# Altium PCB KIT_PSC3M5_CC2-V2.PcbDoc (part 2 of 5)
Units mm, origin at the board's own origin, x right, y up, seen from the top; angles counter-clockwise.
Board outline 131.5 x 87 mm, 6 copper layers (Top Layer, Int1 (GND), Int2 (Sign), Int3 (Sign), Int4 (PWR), Bottom Layer), stack 1.551 mm thick; 371 components, 253 nets, 1359 pads, 837 vias.
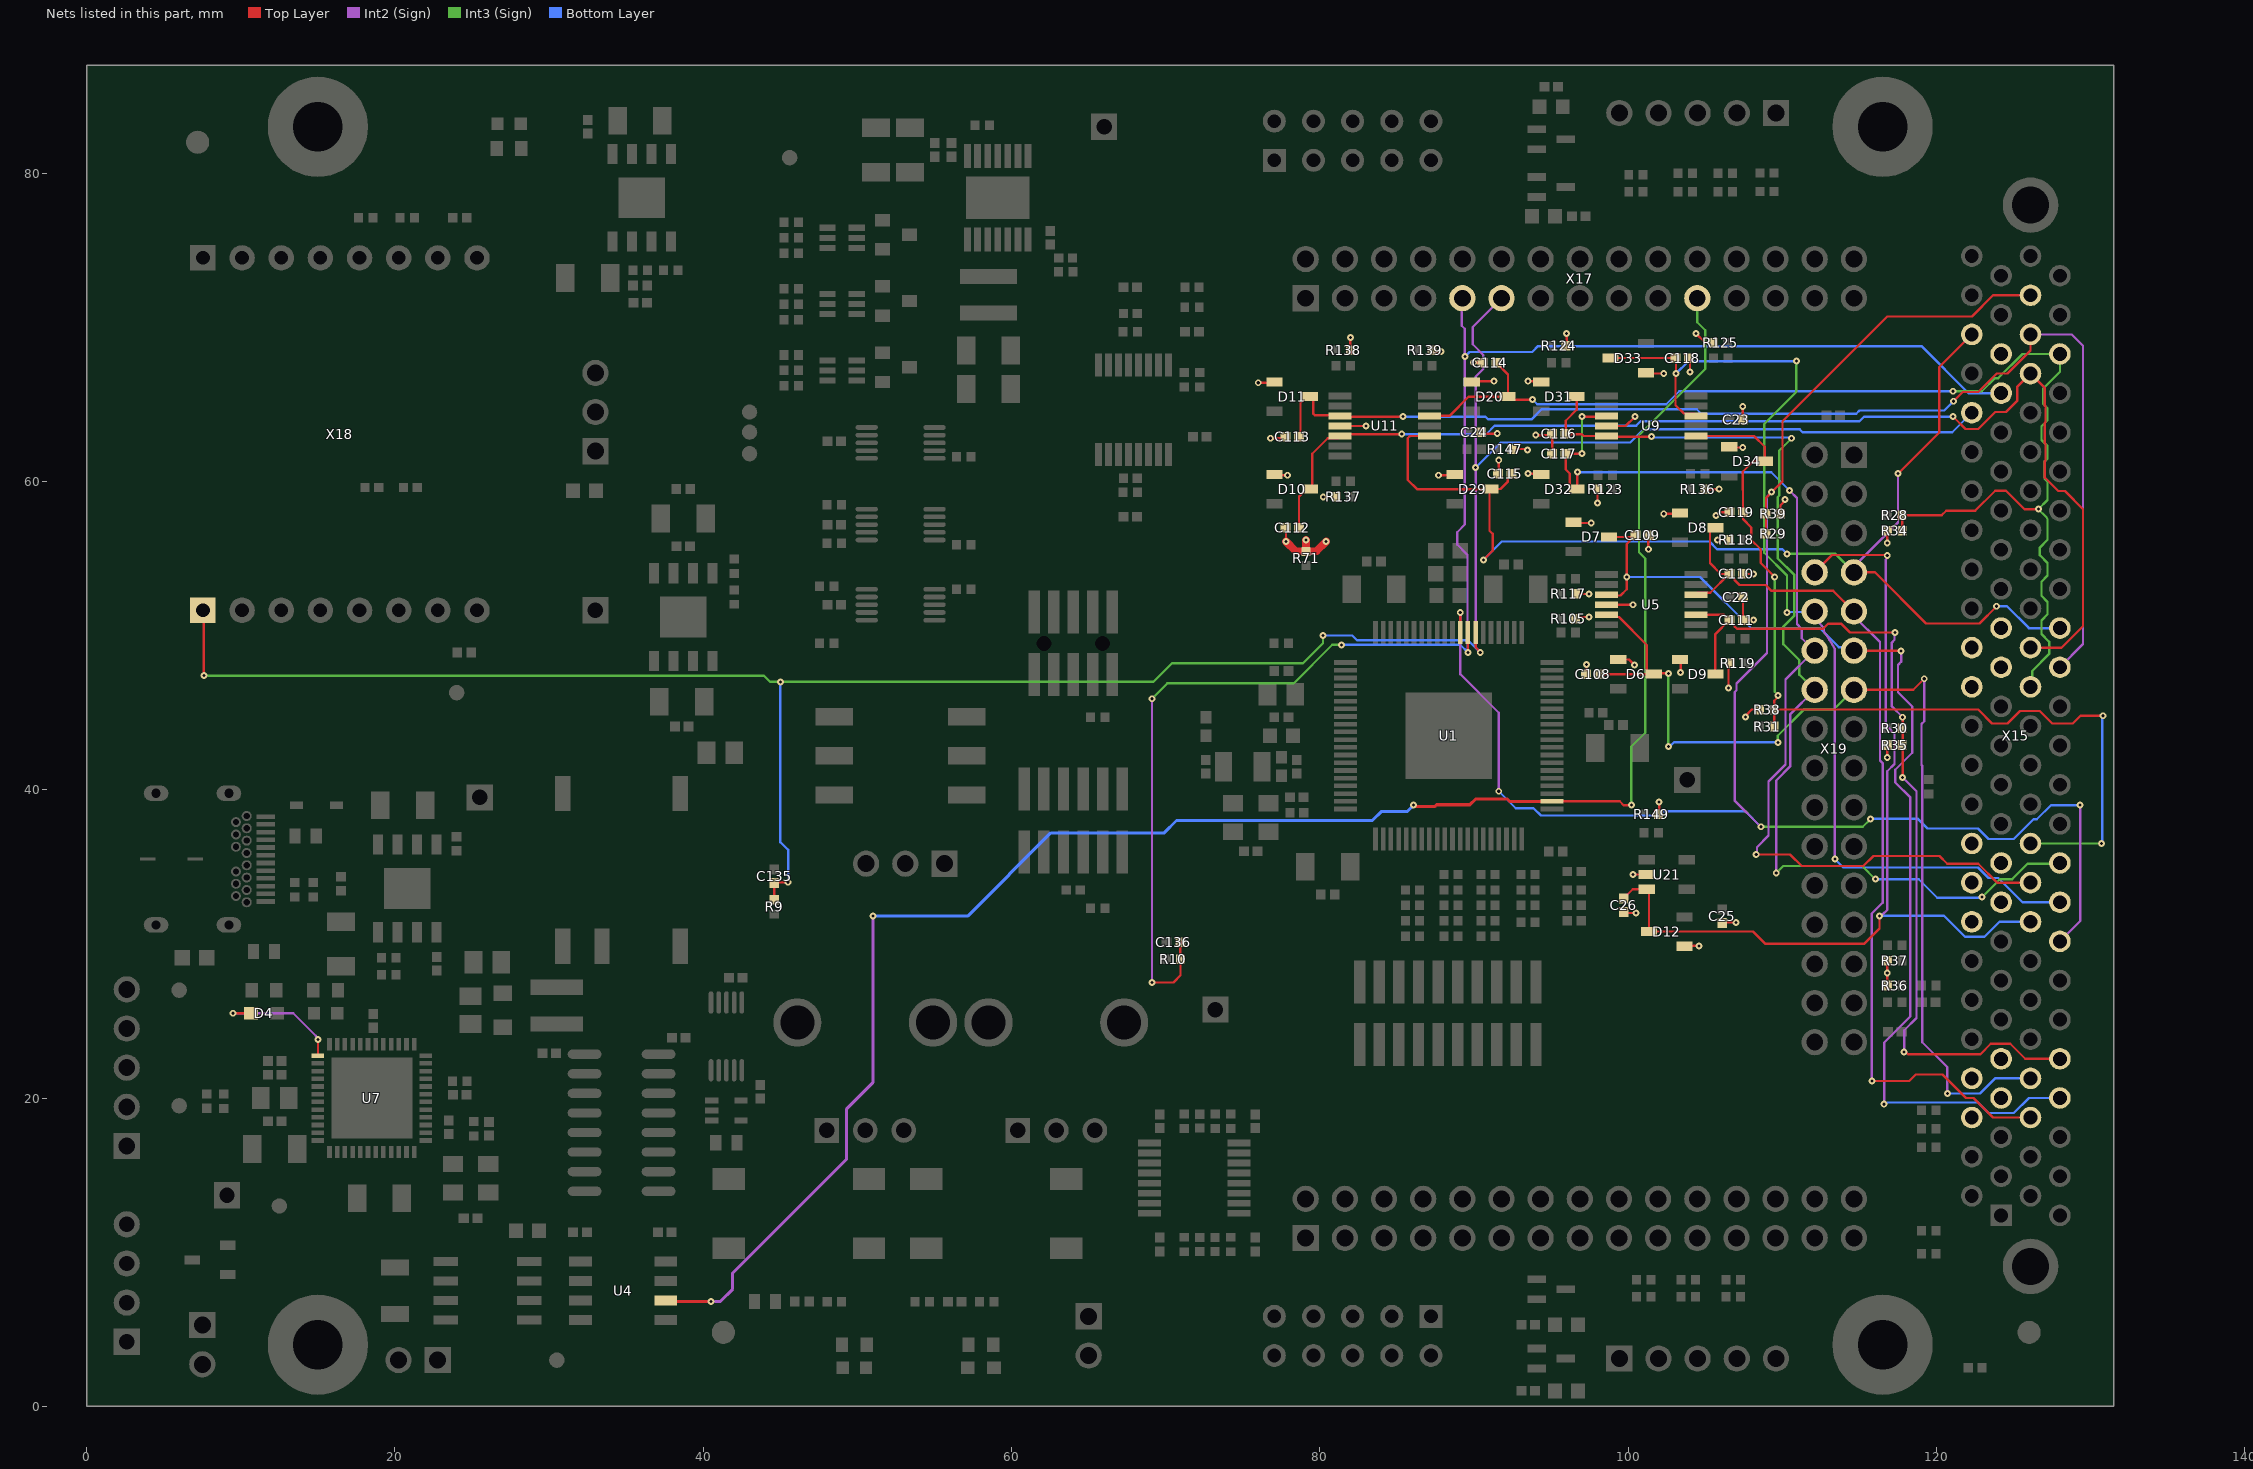
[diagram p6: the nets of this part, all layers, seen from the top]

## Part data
ADJ_1 ADJ_2 ADJ_3: library part Fiducial_Round_1.5mm, "Fiducial Round 1.5mm Copper, 3mm Soldermask", PartNumber=-NoPartNumber-
C1 C6 C7 C8 C9 C10 C14 C16 C28 C43 C75 C76 C127 C132: library part 507459, "CAP / CERA / 100nF / 50V / 10% / X7R (EIA) / -55°C to 125°C / 0402(1005) / SMD / -", Manufacturer="TDK Corporation", Package Description="Capacitor,non-polarized,Chip;1.00mm L X 0.50mm W X 0.60mm H", Package Imperial=0402, Package Metric=1005, Temperature max=125, Temperature min=-55, Temperature Range=Military, Tolerance Neg=10%, Voltage DC (max)=50V
C2 C17 C21 C107: library part 668123, "CAP / CERA / 1uF / 25V / 10% / X7R (EIA) / -55°C to 125°C / 0603(1608) / SMD / -", Manufacturer=Samsung, Package Description="Capacitor,non-polarized,Chip;1.60mm L X 0.80mm W X 0.90mm H", Package Imperial=0603, Package Metric=1608, Supplier Part Number 1=3013415, Temperature max=125, Temperature min=-55, Temperature Range=Military, Tolerance Neg=10%, Voltage DC (max)=25V
C3 C4 C5 C11 C13 C15 C42 C44 C45 C47 C100 C101 C105 C106 C128 C130: library part 282249, "CAP / CERA / 10uF / 50V / 20% / X5R (EIA) / -55°C to 85°C / 1206(3216) / SMD / -", Manufacturer=MuRata, Package Description="Capacitor,non-polarized,Chip;3.20mm L X 1.60mm W X 1.80mm H", Package Imperial=1206, Package Metric=3216, Supplier Part Number 1=2611954, Temperature max=85, Temperature min=-55, Temperature Range=Military, Tolerance Neg=20%, Voltage DC (max)=50V
C12 C41 C126: library part 264563, "CAP / CERA / 10nF / 16V / 5% / X7R (EIA) / -55°C to 125°C / 0402(1005) / SMD / -", Legacy PartNumber=CAP01001706, Manufacturer=MuRata, Package Description="Capacitor,non-polarized,Chip;1.00mm L X 0.50mm W X 0.55mm H", Package Imperial=0402, Package Metric=1005, Temperature max=125, Temperature min=-55, Temperature Range=Military, Tolerance Neg=5%, Voltage DC (max)=16V
C18 C51 C62 C64 C80: library part 673682, "CAP / CERA / 4.7uF / 25V / 20% / X7R (EIA) / -55°C to 125°C / 0805 / SMD / -", Manufacturer=Yageo, Package Description="Capacitor,non-polarized,Chip;2.00mm L X 1.25mm W X 1.45mm H", Supplier Part Number 1=3760019, Temperature max=125, Temperature min=-55, Temperature Range=Military, Tolerance Neg=20%, Voltage DC (max)=25V
C19 C20 C22 C23 C24 C25 C29 C32 C34 C36 C38 C40 C46 C48 C49 C50 C52 C53 C63 C65 C77 C78 C81 C82 C102 C104 C124 C125 C129 C131: library part 310625, "CAP / CERA / 100nF / 50V / 10% / X7R (EIA) / -55°C to 125°C / 0402(1005) / SMD / -", Legacy PartNumber=CAP01010920, Manufacturer=MuRata, Package Description="Capacitor,non-polarized,Chip;1.00mm L X 0.50mm W X 0.55mm H", Package Imperial=0402, Package Metric=1005, Supplier Part Number 1=2611912, Temperature max=125, Temperature min=-55, Temperature Range=Military, Tolerance Neg=10%, Voltage DC (max)=50V
C26 C108 C109 C110 C112 C113 C114 C116 C117 C118: library part 287086, "CAP / CERA / 1nF / 50V / 10% / X7R (EIA) / -55°C to 125°C / 0402(1005) / SMD / -", Legacy PartNumber=CAP01006490, Manufacturer=MuRata, Package Description="Capacitor,non-polarized,Chip;1.00mm L X 0.50mm W X 0.55mm H", Package Imperial=0402, Package Metric=1005, Temperature max=125, Temperature min=-55, Temperature Range=Military, Tolerance Neg=10%, Voltage DC (max)=50V
C33 C35 C37 C39: library part 668123, "CAP / CERA / 1uF / 25V / 10% / X7R (EIA) / -55°C to 125°C / 0603 / SMD / -", Manufacturer=Samsung, Package Description="Capacitor,non-polarized,Chip;1.60mm L X 0.80mm W X 0.90mm H", Supplier Part Number 1=3013415, Temperature max=125, Temperature min=-55, Temperature Range=Military, Tolerance Neg=10%, Voltage DC (max)=25V
C70 C73 C87 C88: library part 287311, "CAP / CERA / 15pF / 50V / 2% / C0G (EIA) / NP0 / -55°C to 125°C / 0402(1005) / SMD / -", Legacy PartNumber=CAP01006535, Manufacturer=MuRata, Package Description="Capacitor,non-polarized,Chip;1.00mm L X 0.50mm W X 0.55mm H", Package Imperial=0402, Package Metric=1005, Temperature max=125, Temperature min=-55, Temperature Range=Military, Tolerance Neg=2%, Voltage DC (max)=50V
C74 C89 C90 C94 C95 C96 C135 C136 C137 C138 C139: library part 289336, "CAP / CERA / 15nF / 50V / 20% / X7R (EIA) / -55°C to 125°C / 0402(1005) / SMD / -", Legacy PartNumber=CAP01006940, Manufacturer=MuRata, Package Description="Capacitor,non-polarized,Chip;1.00mm L X 0.50mm W X 0.55mm H", Package Imperial=0402, Package Metric=1005, Temperature max=125, Temperature min=-55, Temperature Range=Military, Tolerance Neg=20%, Voltage DC (max)=50V
C85 C86: library part 287356, "CAP / CERA / 18pF / 50V / 1% / C0G (EIA) / NP0 / -55°C to 125°C / 0402(1005) / SMD / -", Legacy PartNumber=CAP01006544, Manufacturer=MuRata, Package Description="Capacitor,non-polarized,Chip;1.00mm L X 0.50mm W X 0.55mm H", Package Imperial=0402, Package Metric=1005, Temperature max=125, Temperature min=-55, Temperature Range=Military, Tolerance Neg=1%, Voltage DC (max)=50V
C103: library part 289386, "CAP / CERA / 2.2nF / 50V / 20% / X7R (EIA) / -55°C to 125°C / 0402(1005) / SMD / -", Legacy PartNumber=CAP01006950, Manufacturer=MuRata, Package Description="Capacitor,non-polarized,Chip;1.00mm L X 0.50mm W X 0.55mm H", Package Imperial=0402, Package Metric=1005, Temperature max=125, Temperature min=-55, Temperature Range=Military, Tolerance Neg=20%, Voltage DC (max)=50V
C111 C115 C119: library part 286936, "CAP / CERA / 22pF / 50V / 5% / C0G (EIA) / NP0 / -55°C to 125°C / 0402(1005) / SMD / -", Legacy PartNumber=CAP01006460, Manufacturer=MuRata, Package Description="Capacitor,non-polarized,Chip;1.00mm L X 0.50mm W X 0.55mm H", Package Imperial=0402, Package Metric=1005, Temperature max=125, Temperature min=-55, Temperature Range=Military, Tolerance Neg=5%, Voltage DC (max)=50V
D1: library part 678278, "Chip LED, 589nm, Yellow, Electronic Equipment Applications", Manufacturer="OSRAM Opto Semiconductors", Package Description="LED,Side Concave;2 pin,1.60mm W X 0.80mm L X 0.40mm H", Temperature max=85, Temperature min=-30, Temperature Range=Military, Voltage DC (max)=na
D2 D4: library part 494911, "ChipLED 0603, Red, 633nm, Temp Raneg(-30 to 85°C)", Manufacturer="OSRAM Opto Semiconductors", Package Description="LED,Side Concave;2 pin,1.60mm W X 0.80mm L X 0.80mm H", Temperature max=85, Temperature min=-30, Temperature Range=Military, Voltage DC (max)=na
D3 D5: library part 678273, "Chip LED, 573nm, Green, Electronic Equipment Applications", Manufacturer="OSRAM Opto Semiconductors", Package Description="LED,Side Concave;2 pin,1.60mm W X 0.80mm L X 0.40mm H", Supplier Part Number 1=2575345, Temperature max=85, Temperature min=-30, Temperature Range=Military, Voltage DC (max)=na
D6 D7 D8 D9 D10 D11 D12 D20 D29 D31 D32 D33 D34: library part 394146, "Dual Series Small Signal Schottky Diodes", Legacy PartNumber=DIO01300188, Manufacturer=Vishay, Package Description="SOT,0.95mm pitch;3 pin,1.315mm W X 2.95mm L X 1.15mm H body", Supplier Part Number 1=1612328, Temperature max=125, Temperature min=-55, Temperature Range=Military, Voltage DC (max)=na
D21: library part 420617, "Medium Power AF Schottky Diode", Legacy PartNumber=IFX01400145, Manufacturer="Infineon Technologies", Package Description=SOD323, Temperature max=125, Temperature min=-65, Temperature Range=Military, Voltage DC (max)=na
D30: library part 527432, "CAN bus ESD protection diode", Manufacturer=Nexperia, Package Description="SOT,0.95mm pitch;3 pin,1.30mm W X 2.90mm L X 1.10mm H body", Supplier Part Number 1=1510712, Temperature max=150, Temperature min=-55, Temperature Range=Military, Voltage DC (max)=na
JP1 X28 X30: library part 382904, "Through hole .025 SQ Post Header, 2.54mm pitch, 2 pin, vertical, single row", Legacy PartNumber=CON01500574, Manufacturer=Samtec, Package Description="Header,vertical,2.54mm pitch;0.64mm lead width,2 pins,1 row,2 pins per row,5.08mm L X 2.54mm W X 8.636mm H body", Supplier Part Number 1=2667448, Temperature max=125, Temperature min=-55, Temperature Range=Military, Voltage DC (max)=na
L1: library part BLM18PG600SN1D, "FERRITE, SMD, 60 OHM, 0603", Manufacturer=Murata, PartNumber=01.30.0224.0, Supplier Part Number 1=490-1036-2-ND
L2 L4: library part BLM18KG102SN1D, "FERRITE, SMD, 1000 OHM, 0.8A, 0603", Manufacturer=Murata, PartNumber=01.30.0521.0
L3: library part 325876, "IND / STD / 4.7uH / 5.1A / 20% / -40°C to 125°C / 44.1R / SMD Type / Inductor,Chip;4.00mm L X 4.00mm W X 3.10mm H / SMD / -", Legacy PartNumber=IND00702665, Manufacturer=Coilcraft, Package Description="Inductor,Chip;4.00mm L X 4.00mm W X 3.10mm H", Supplier Part Number 1=2289056, Temperature max=125, Temperature min=-40, Temperature Range=Automotive, Tolerance Neg=20%, Voltage DC (max)=na
L5: "FERRITE, SMD, 30 OHM, 4000mA, 0805", Manufacturer=Murata, PartNumber=01.30.0266.0, Supplier Part Number 1=490-1052-1-ND
L6: "2.2uH - Isat 5.6A", Manufacturer=Coilcraft, PartNumber=01.30.0326.0
MH1 MH2 MH3 MH4: library part Mounting_Hole_M3, PartNumber=-NoPartNumber-
Q1 Q8 Q9 Q10: "PNP-Digital Transistor  50V, 100mA, R1=R2=47k, SOT-323", Manufacturer="Infineon Technologies AG", Manufacturer (2nd Source)=Nexperia, ManufacturerPartNo (2nd Source)=PDTA144EU,115, PartNumber=00.94.0133.0, Supplier Part Number 1=2156-PDTA144EU,115-ND
Q2 Q5 Q7: library part BCM8575BS,115, "Dual PNP/PNP, Vceo -45V, Ic -100mA, hFE 290, AEC-Q", Manufacturer=Nexperia, ManufacturerPartNo=BCM857BS,115, PartNumber=00.94.0374.0, Supplier Part Number 1=1727-4883-2-ND
Q3 Q4 Q6: library part 400833, "HEXFET P-Channel Power MOSFET, 20V, 3.7A", Manufacturer="Infineon Technologies", Package Description="SOT,0.95mm pitch;3 pin,1.30mm W X 2.92mm L X 1.12mm H body", Supplier Part Number 1=2363354, Temperature max=150, Temperature min=-55, Temperature Range=Military, Voltage DC (max)=na
R1 R2: library part Solderbridge_2Pad_0R_0402, "SMD solderbridge, 2 Pads, 0R resistor populated, 0402 size", PartNumber=01.02.0902.0
R3 R4 R8 R11 R12 R13 R15 R17 R25 R26 R47 R56 R58 R60 R62 R71 R72 R74 R76 R78 R79 R80 R81 R82 R83 R87 R88 R89 R90 R92 R94 R95 R96 R97 R98 R103 R104 R108: library part 327372, "RES / STD / 0R / 63mW / 0R / 0ppm/K / -55°C to 155°C / 0402(1005) / SMD / -", Legacy PartNumber=RES00000001, Manufacturer=Yageo, Package Imperial=0402, Package Metric=1005, Temperature max=155, Temperature min=-55, Temperature Range=Military, Voltage DC (max)=50V
R5 R53: library part 345982, "RES / STD / 4.7k / 100mW / 1% / 100ppm/K / -55°C to 155°C / 0603(1608) / SMD / -", Legacy PartNumber=RES01801219, Manufacturer=Vishay, Package Imperial=0603, Package Metric=1608, Temperature max=155, Temperature min=-55, Temperature Range=Military, Tolerance Neg=1%, Voltage DC (max)=75V
R6 R7: library part 675198, "RES / VAR / 10k / 50mW / 20% / - / -10°C to 50°C /  THT, 2.5 mm pitch, 11.80 mm L X 10 mm W X 20.5 mm H body / - / -", Manufacturer=Bourns, Package Description="Potentiometer; THT, 2.5 mm pitch, 11.80 mm L X 10 mm W X 20.5 mm H body", Supplier Part Number 1=2519610, Temperature max=50, Temperature min=-10, Temperature Range=Military, Tolerance Neg=20%, Voltage DC (max)=20V
R9 R10 R126: library part 327441, "RES / STD / 100R / 63mW / 1% / 100ppm/K / -55°C to 155°C / 0402(1005) / SMD / -", Manufacturer=Yageo, Package Description="Resistor,Chip;1.00mm L X 0.50mm W X 0.40mm H", Package Imperial=0402, Package Metric=1005, Supplier Part Number 1=9239111, Temperature max=155, Temperature min=-55, Temperature Range=Military, Tolerance Neg=1%
R14 R24 R70 R75 R91 R99 R114 R115 R116 R120 R121 R122 R127 R128 R129 R130 R140 R143 R144 R145: library part 342167, "RES / STD / 10k / 63mW / 1% / 100ppm/K / -55°C to 155°C / 0402(1005) / SMD / -", Legacy PartNumber=RES01800457, Manufacturer=Vishay, Package Imperial=0402, Package Metric=1005, Temperature max=155, Temperature min=-55, Temperature Range=Military, Tolerance Neg=1%, Voltage DC (max)=50V
R16 R28 R29 R30 R31 R40 R41 R42 R43 R44 R45 R46 R51 R55 R57 R59 R61 R148 R150 R152: library part 341597, "RES / STD / 1k / 63mW / 1% / 100ppm/K / -55°C to 155°C / 0402(1005) / SMD / -", Legacy PartNumber=RES01800343, Manufacturer=Vishay, Package Imperial=0402, Package Metric=1005, Temperature max=155, Temperature min=-55, Temperature Range=Military, Tolerance Neg=1%, Voltage DC (max)=50V
R18 R21: library part 346002, "RES / STD / 5.1k / 100mW / 1% / 100ppm/K / -55°C to 155°C / 0603(1608) / SMD / -", Legacy PartNumber=RES01801223, Manufacturer=Vishay, Package Imperial=0603, Package Metric=1608, Temperature max=155, Temperature min=-55, Temperature Range=Military, Tolerance Neg=1%, Voltage DC (max)=75V
R19 R20: library part 340637, "RES / STD / 22R / 63mW / 1% / 100ppm/K / -55°C to 155°C / 0402 / SMD / -", Legacy PartNumber=RES01800151, Manufacturer=Vishay, Temperature max=155, Temperature min=-55, Temperature Range=Military, Tolerance Neg=1%, Voltage DC (max)=50V
R22: library part 327541, "RES / STD / 4.7k / 63mW / 1% / 100ppm/K / -55°C to 155°C / 0402(1005) / SMD / -", Manufacturer=Yageo, Package Description="Resistor,Chip;1.00mm L X 0.50mm W X 0.40mm H", Package Imperial=0402, Package Metric=1005, Supplier Part Number 1=9239316, Temperature max=155, Temperature min=-55, Temperature Range=Military, Tolerance Neg=1%, Voltage DC (max)=50V
R23: library part 341427, "RES / STD / 510R / 63mW / 1% / 100ppm/K / -55°C to 155°C / 0402(1005) / SMD / -", Legacy PartNumber=RES01800309, Manufacturer=Vishay, Package Imperial=0402, Package Metric=1005, Temperature max=155, Temperature min=-55, Temperature Range=Military, Tolerance Neg=1%, Voltage DC (max)=50V
R27 R50 R54 R64 R68: library part 342737, "RES / STD / 100k / 63mW / 1% / 100ppm/K / -55°C to 155°C / 0402 / SMD / -", Legacy PartNumber=RES01800571, Manufacturer=Vishay, Temperature max=155, Temperature min=-55, Temperature Range=Military, Tolerance Neg=1%, Voltage DC (max)=50V
R32 R33: library part 341027, "RES / STD / 100R / 63mW / 1% / 100ppm/K / -55°C to 155°C / 0402(1005) / SMD / -", Legacy PartNumber=RES01800229, Manufacturer=Vishay, Package Imperial=0402, Package Metric=1005, Temperature max=155, Temperature min=-55, Temperature Range=Military, Tolerance Neg=1%, Voltage DC (max)=50V
R34 R35 R38: library part 342737, "RES / STD / 100k / 63mW / 1% / 100ppm/K / -55°C to 155°C / 0402(1005) / SMD / -", Legacy PartNumber=RES01800571, Manufacturer=Vishay, Package Imperial=0402, Package Metric=1005, Temperature max=155, Temperature min=-55, Temperature Range=Military, Tolerance Neg=1%, Voltage DC (max)=50V
R36 R37: library part 342327, "RES / STD / 20k / 63mW / 1% / 100ppm/K / -55°C to 155°C / 0402(1005) / SMD / -", Legacy PartNumber=RES01800489, Manufacturer=Vishay, Package Imperial=0402, Package Metric=1005, Temperature max=155, Temperature min=-55, Temperature Range=Military, Tolerance Neg=1%, Voltage DC (max)=50V
R39: library part 342897, "RES / STD / 200k / 63mW / 1% / 100ppm/K / -55°C to 155°C / 0402(1005) / SMD / -", Legacy PartNumber=RES01800603, Manufacturer=Vishay, Package Imperial=0402, Package Metric=1005, Temperature max=155, Temperature min=-55, Temperature Range=Military, Tolerance Neg=1%, Voltage DC (max)=50V
R48 R49 R141 R142: library part 341777, "RES / STD / 2.2k / 63mW / 1% / 100ppm/K / -55°C to 155°C / 0402(1005) / SMD / -", Legacy PartNumber=RES01800379, Manufacturer=Vishay, Package Imperial=0402, Package Metric=1005, Temperature max=155, Temperature min=-55, Temperature Range=Military, Tolerance Neg=1%, Voltage DC (max)=50V
R52 R63 R65 R66 R67 R69 R106: library part 342167, "RES / STD / 10k / 63mW / 1% / 100ppm/K / -55°C to 155°C / 0402 / SMD / -", Legacy PartNumber=RES01800457, Manufacturer=Vishay, Temperature max=155, Temperature min=-55, Temperature Range=Military, Tolerance Neg=1%, Voltage DC (max)=50V
R73: library part 353082, "RES / STD / 120R / 250mW / 1% / 100ppm/K / -55°C to 155°C / 1206(3216) / SMD / -", Legacy PartNumber=RES01802637, Manufacturer=Vishay, Package Imperial=1206, Package Metric=3216, Temperature max=155, Temperature min=-55, Temperature Range=Military, Tolerance Neg=1%, Voltage DC (max)=200V
R77 R93 R105 R117 R118 R119 R123 R124 R125 R136 R137 R138 R139 R147 R149: library part 341752, "RES / STD / 1.96k / 63mW / 1% / 100ppm/K / -55°C to 155°C / 0402(1005) / SMD / -", Legacy PartNumber=RES01800374, Manufacturer=Vishay, Package Imperial=0402, Package Metric=1005, Temperature max=155, Temperature min=-55, Temperature Range=Military, Tolerance Neg=1%, Voltage DC (max)=50V
R84 R85 R86 R100 R101 R102 R151 R153 R155 R157 R159 R160: library part 341067, "RES / STD / 120R / 63mW / 1% / 100ppm/K / -55°C to 155°C / 0402(1005) / SMD / -", Legacy PartNumber=RES01800237, Manufacturer=Vishay, Package Imperial=0402, Package Metric=1005, Temperature max=155, Temperature min=-55, Temperature Range=Military, Tolerance Neg=1%, Voltage DC (max)=50V
R107: library part 341597, "RES / STD / 1k / 63mW / 1% / 100ppm/K / -55°C to 155°C / 0402 / SMD / -", Legacy PartNumber=RES01800343, Manufacturer=Vishay, Temperature max=155, Temperature min=-55, Temperature Range=Military, Tolerance Neg=1%, Voltage DC (max)=50V
R109 R110 R111 R112 R113: library part 330423, "RES / STD / 680R / 100mW / 1% / 100ppm/K / -55°C to 155°C / 0603(1608) / SMD / -", Manufacturer=Yageo, Package Description="Resistor,Chip;1.60mm L X 0.80mm W X 0.55mm H", Package Imperial=0603, Package Metric=1608, Temperature max=155, Temperature min=-55, Temperature Range=Military, Tolerance Neg=1%, Voltage DC (max)=75V
R131 R133 R135: library part 342592, "RES / STD / 56k / 63mW / 1% / 100ppm/K / -55°C to 155°C / 0402(1005) / SMD / -", Legacy PartNumber=RES01800542, Manufacturer=Vishay, Package Imperial=0402, Package Metric=1005, Temperature max=155, Temperature min=-55, Temperature Range=Military, Tolerance Neg=1%, Voltage DC (max)=50V
R132: library part 342302, "RES / STD / 18k / 63mW / 1% / 100ppm/K / -55°C to 155°C / 0402(1005) / SMD / -", Legacy PartNumber=RES01800484, Manufacturer=Vishay, Package Imperial=0402, Package Metric=1005, Temperature max=155, Temperature min=-55, Temperature Range=Military, Tolerance Neg=1%, Voltage DC (max)=50V
R134 R146: library part 342452, "RES / STD / 33k / 63mW / 1% / 100ppm/K / -55°C to 155°C / 0402(1005) / SMD / -", Legacy PartNumber=RES01800514, Manufacturer=Vishay, Package Imperial=0402, Package Metric=1005, Temperature max=155, Temperature min=-55, Temperature Range=Military, Tolerance Neg=1%, Voltage DC (max)=50V
R162 R163: library part 341882, "RES / STD / 3.3k / 63mW / 1% / 100ppm/K / -55°C to 155°C / 0402(1005) / SMD / -", Legacy PartNumber=RES01800400, Manufacturer=Vishay, Package Imperial=0402, Package Metric=1005, Temperature max=155, Temperature min=-55, Temperature Range=Military, Tolerance Neg=1%, Voltage DC (max)=50V
SW1 SW2: library part 376475, "Micro Miniature Pushbutton Switch", Legacy PartNumber=SW0000003, Manufacturer="Tyco Electronics", Package Description="Switch,Push button ,4.5mm Pitch,Vertical, 6mm L X 6mm W X 5.4mm H body", Supplier Part Number 1=3801287, Temperature max=85, Temperature min=-35, Temperature Range=Military, Voltage DC (max)=na
SW3: library part DIPSW-3, "RM2.54, 3polig, SMD, ON-Position", Manufacturer=CTS, Supplier Part Number 1=CT2194LPST-ND
TP1 TP2 TP3 TP4 TP5 TP6 TP7 TP8 TP9: library part Testpad_Round, "Testpad SMD / THT", PartNumber=-NoPartNumber-
U1: "PSoC C3 Main Line, Cortex-M33, 180 MHz, 64KB SRAM, 256KB Flash, E-LQFP-80", Manufacturer="Infineon Technologies AG"
U2 U8 U14: library part 592428, "Micropower, low noise, low dropout voltage regulator, Designed for use in battery-powered systems, the low quiescent current of 30 µA makes it an ideal choice", Manufacturer="Infineon Technologies", Package Description="SOIC,1.27mm pitch;8 pin,3.90mm W X 4.90mm L X 1.70mm H body (w/thermal tab)", Supplier Part Number 1=2710078, Temperature max=125, Temperature min=-40, Temperature Range=Automotive, Voltage DC (max)=na
U3 U6: library part 767058, "Low Voltage High Speed Quadruple Differential Line Receiver With 15 KV IEC ESD Protection", Manufacturer="Texas Instruments", Package Description="SOP,0.65mm pitch;16 pin,4.40mm W X 5.00mm L X 1.20mm H body", Supplier Part Number 1=3121139, Temperature max=85, Temperature min=-40, Temperature Range=Industrial, Voltage DC (max)=na
U4: "Robust Digital Isolator, 1 Forward 1 Reverse Channel Configuration", Manufacturer="Infineon Technologies"
U5 U9 U11: library part 403536, "Precision, 20MHz, CMOS, Quad Rail-to-Rail Input/Output Operational Amplifier", Legacy PartNumber=IC02600068, Manufacturer="Analog Devices", Supplier Part Number 1=1660999, Temperature max=0, Temperature Range=Military, Voltage DC (max)=na
U7: library part 419942, "Microcontroller Series for Industrial Applications", Manufacturer="Infineon Technologies", Package Description="QFN,0.50mm pitch,square;48 pin,7.00mm L X 7.00mm W X 0.90mm H body (w/thermal tab)", Supplier Part Number 1=2839389, Temperature max=125, Temperature min=-40, Temperature Range=Automotive, Voltage DC (max)=na
U10: library part Si8662BB-B-IS1, "6-Ch Digital Isolator (4xIn / 2xOut), 150Mbit/s, 2500Vrms, SOIC-16, active low", Manufacturer="Skyworks Solutions Inc.", PartNumber=00.81.0252.0, Supplier Part Number 1=SI8662BB-B-IS1-ND
U12: "Single Gate Buffer/Driver, OE high active, 1.65V - 5.5V, SC70-5", Manufacturer="Texas Instruments", ManufacturerPartNo=SN74LVC1G126DCKR, PartNumber=00.29.0112.0, Supplier Part Number 1=296-11606-1-ND
U13: library part 694499, "CAN signal improvement transceiver", Manufacturer="Infineon Technologies", Package Description="SOIC,1.27mm pitch;8 pin,3.94mm W X 4.93mm L X 1.73mm H body", Temperature max=150, Temperature min=-40, Temperature Range=Automotive, Voltage DC (max)=na
U15 U17 U18 U19: "TS5A23157DGSR, 1.8V-5V, 2:1 (SPDT), 2-channel analog switch, 10R", Manufacturer="Texas Instruments", PartNumber=00.30.0133.0
U16: library part 513815, "OPTIREG Switcher 2.8 MHz Synchronous Step-Down Regulator, 2.5A, 5V, Input voltage 3.7 V to 35 V", Manufacturer="Infineon Technologies", Package Description="SOP,0.65mm pitch;14 pin,3.90mm W X 4.90mm L X 1.15mm H body (w/thermal tab)", Temperature max=150, Temperature min=-40, Temperature Range=Automotive, Voltage DC (max)=na
U20: library part IES0205S07, "Isolated DC/DC Converter, 5V/7V, 286mA, 2W, SMD, 3kV Iso, unregulated", Manufacturer="XP Power", Supplier Part Number 1=209-IES0205S07
U21: library part 413062, "Single Precision, 20MHz, CMOS, Rail-to-Rail Input/Output Operational Amplifier", Legacy PartNumber=IC02600931, Manufacturer="Analog Devices", Supplier Part Number 1=9079408RL, Temperature max=0, Temperature Range=Military, Voltage DC (max)=na
X1: library part 387533, "SMT Micro Header, 1.27mm Pitch, 20 pins, Vertical, Double Row, Keying Shroud", Legacy PartNumber=CON01501020, Manufacturer=Samtec, Package Description="Header, Vertical, 1.27mm Pitch; 20 Pins, 2 rows, 10 Pins per row, 12.7mm L X 5.08mm W X 6.375mm H body", Temperature max=125, Temperature min=-55, Temperature Range=Military, Voltage DC (max)=na
X2 X4: library part 673740, "Header, 4-Wall Lo-PRO, .100, Straight, 10Pins, 2.54mm Pitch", Manufacturer=3M, Package Description="Connector, THT, 2.54 mm pitch, 10 pin, 8.59 mm L X 20.02 mm W X 10.04 mm H body", Supplier Part Number 1=9838244, Temperature max=105, Temperature min=-55, Temperature Range=Military, Voltage DC (max)=na
X3 X7: library part 646168, "PCB terminal block, nominal current: 6 A, rated voltage (III/2)Number of positions per row: 5, pitch: 2.54 mm", Manufacturer="Phoenix Contact", Package Description="Terminal Block, THT, 2.54 mm pitch, 5 pin, 13.16 mm L X 6.20 mm W X 8.65 mm H body", Supplier Part Number 1=2776439, Temperature max=105, Temperature min=-40, Temperature Range=Industrial, Voltage DC (max)=na
X10: library part 632723300011, "USB 3.1 Type C, Receptacle, Horizontal, THR/SMT, 24 Pin, 5A, 20V, -40 to +105degC", Manufacturer="Wurth Elektronik", PartNumber=03.16.0206.0
X11: library part 638279, "Connector Header Surface Mount 12 position 0.050 (1.27mm)", Manufacturer=Samtec, Package Description="Connector, SMD, 1.27 mm pitch, 12 pin, 3.43 mm L X 7.62 mm W X 6.38 mm H body", Supplier Part Number 1=2856442, Temperature max=125, Temperature min=-55, Temperature Range=Military, Voltage DC (max)=na
X12: library part 382494, "SMT Micro Header, 1.27mm pitch, 10 pin, Vertical, Double Row, Keying Shroud with Alignment pin, DAP", Manufacturer=Samtec, Package Description="Header, vertical, 1.27mm pitch; 10 pins, 2 rows, 5 pins per row, 6.35mm L X 5.08mm W X 6.223mm H body", Temperature max=125, Temperature min=-55, Temperature Range=Military, Voltage DC (max)=na
X13: library part 654247, "WR-PHD 2.54 mm Pitch, 5Pins, THT Pin Header", Manufacturer="Wurth Elektronik", Package Description="Connector, THT; 2.54mm Pitch, 5 Pins, 12.70 mm L X 2.54 mm W X 8.89 mm H body", Supplier Part Number 1=2356157, Temperature max=105, Temperature min=-40, Temperature Range=Industrial, Voltage DC (max)=na
X14: library part 378014, "Header, THT, Single Row, Vertical, 2.54mm, 4 Pins", Manufacturer="TE Connectivity", Package Description="Header,vertical,2.54mm pitch;0.63mm lead width,4 pins,1 row,4 pins per row,10.16mm L X 2.5mm W X 8.6mm H body", Supplier Part Number 1=1248151, Temperature max=105, Temperature min=-65, Temperature Range=Military, Voltage DC (max)=na
X15: "Hirose FX2 Series 1.27mm 100 Way 2 Row Right Angle PCB Socket Surface Mount Board to Board", Manufacturer_Name=Hirose, Manufacturer_Part_Number=FX2-100S-1.27DSL(71), Mouser Part Number=798-FX2100S127DSL71
X16 X17: library part 377714, "Through-Hole 0.635mm Sq. Double Row Vertical Post Header", Legacy PartNumber=CON01500070, Manufacturer=Samtec, Package Description="Header,vertical,2.54mm pitch;0.64mm lead width,30 pins,2 rows,15 pins per row,38.10mm L X 5.02mm W X 8.38mm H body", Supplier Part Number 1=2011036, Temperature max=125, Temperature min=-55, Temperature Range=Military, Voltage DC (max)=na
X18: library part mikroBUS_Host, "mikroBUS Socket"
X19: library part 378123, "Through hole .025 SQ Post Header, 2.54mm pitch, 32 pin, vertical, double row", Legacy PartNumber=CON01500107, Manufacturer=Samtec, Package Description="Header,vertical,2.54mm pitch;0.64mm lead width,32 pins,2 rows,16 pins per row,40.705mm L X 2.54mm W X 8.38mm H body", Supplier Part Number 1=2025347, Temperature max=125, Temperature min=-55, Temperature Range=Military, Voltage DC (max)=na
X20 X29: library part 378477, "Through hole .025 SQ Post Header, 2.54mm pitch, 3 pin, vertical, single row", Legacy PartNumber=CON01500137, Manufacturer=Samtec, Package Description="Header,vertical,2.54mm pitch;0.64mm lead width,3 pins,1 row,3 pins per row,7.62mm L X 2.48mm W X 8.38mm H body", Supplier Part Number 1=1925658, Temperature max=125, Temperature min=-55, Temperature Range=Military, Voltage DC (max)=na
X22 X23 X24 X25 X26 X27: "Wrap-Leiste 1-reihig  1-polig", PartNumber=03.20.0000.0
Y1: library part 16MHz/3225/4PAD, "16MHz 8pF 50ppm/15ppm", Manufacturer=NDK, ManufacturerPartNo="NX3225SA 16MHZ AT-W", PartNumber=00.98.0120.0, Supplier Part Number 1=644-1129-1-ND
Y2: library part 12MHz/3225/4PAD, "12MHz 8pF 50ppm/15ppm", Manufacturer=NDK, ManufacturerPartNo="NX3225SA 12MHZ AT-W", PartNumber=00.98.0092.0, Supplier Part Number 1=644-1128-1-ND
Y3: library part 409415, "SMD Low Profile Crystal, 32.768kHz, Load Capacitance 12.5 pF (Operating Temp -40°C to +85°C)", Legacy PartNumber=IC02600599, Manufacturer="Abracon Corporation", Package Description="Crystal;3.2mm L X 1.50mm W X 0.9mm H", Supplier Part Number 1=2101347, Temperature max=85, Temperature min=-40, Temperature Range=Industrial, Tolerance Neg=20%, Voltage DC (max)=na

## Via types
v1: diameter 0.45, hole 0.2, Top Layer to Bottom Layer, tented both sides, 833 vias
v2: diameter 0.55, hole 0.2, Top Layer to Bottom Layer, tented both sides, 4 vias

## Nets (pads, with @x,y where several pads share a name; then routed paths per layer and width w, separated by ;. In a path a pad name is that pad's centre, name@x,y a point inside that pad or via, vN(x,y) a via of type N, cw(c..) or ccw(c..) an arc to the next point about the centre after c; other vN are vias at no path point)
AGND: C22.1 C23.1 C24.1 C25.1 C26.1 C108.1 C109.1 C110.1 C111.1 C112.1 C113.1 C114.1 C115.1 C116.1 C117.1 C118.1 C119.1 D6.1 D7.1 D8.1 D9.1 D10.1 D11.1 D12.1 D20.1 D29.1 D31.1 D32.1 D33.1 D34.1 R34.1 R35.1 R36.1 R37.1 R38.1 R39.1 R71.2 R105.1 R117.1 R118.1 R119.1 R123.1 R124.1 R125.1 R136.1 R137.1 R138.1 R139.1 R147.1 R149.1 U5.11 U9.11 U11.11 U21.2 X15.A6 X15.A7 X15.A8 X15.A9 X15.A16 X15.A17 X15.A18 X15.A19 X15.A20 X15.A28 X15.A29 X15.A30 X15.A31 X15.A45 | length 57.5
  Top Layer w0.15: v1(76,66.4) 77,66.4 D11.1@77.05,66.45 ; v1(76.8,62.8) 77.66,62.8 C113.1@77.76,62.9 ; D10.1@77.05,60.45 77.1,60.4 v1(77.9,60.4) ; C112.1@77.76,57 77.8,56.96 v1(77.8,56.1) ; v1(80.216,58.99) 81.02,58.99 R137.1@81.03,59 ; U11.11@81.3,63.6 v1(83,63.6) ; R138.1@81.97,68.5 81.975,68.505 v1(81.975,69.347) ; R139.1@87.27,68.5 87.35,68.42 v1(87.841,68.42) ; v1(87.7,60.4) 88.7,60.4 D29.1@88.75,60.45 ; D20.1@89.85,66.45 89.9,66.5 v1(91.3,66.5) ; v1(89.975,67.7) C114.1@90.56,67.7 ; C24.1@90.44,63.2 90.54,63.1 v1(91.5,63.1) ; C114.1@90.525,67.935 C114.1@90.56,67.9 ; C115.1@91.56,60.5 91.6,60.54 v1(91.6,61.375) ; R147.1@92.47,62.1 93.422,62.1 v1(93.475,62.047) ; v1(93.5,60.5) 94.3,60.5 D32.1@94.35,60.45 ; v1(93.5,66.5) 94.3,66.5 D31.1@94.35,66.45 ; v1(94,63) 94.96,63 C116.1@95.06,63.1 C117.1@95.06,61.8 ; R124.1@95.97,68.8 96,68.83 v1(96,69.6) ; D7.1@96.411,57.3 v1(97.6,57.3) ; R105.1@96.57,51.2 v1(97.45,51.2) ; R117.1@96.57,52.7 v1(97.45,52.7) ; C108.1@97.26,47.5 97.3,47.54 v1(97.3,48.125) ; v1(98,58.6) 98,59.47 R123.1@98.03,59.5 ; U5.11@98.6,52 v1(100.3,52) ; U9.11@98.6,63.6 99.828,63.6 v1(100.428,64.2) ; D6.1@99.35,48.45 100.05,48.45 v1(100.4,48.1) ; C26.1@99.7,32.06 99.76,32 v1(100.5,32) ; v1(100.3,34.5) U21.2@101.2,34.5 ; D33.1@101.15,67.05 101.2,67 v1(102.3,67) ; v1(101.3,55.6) 101.3,56.46 C109.1@101.34,56.5 ; R149.1@101.97,38.4 102,38.43 v1(102,39.2) ; v1(102.3,57.9) 103.3,57.9 D8.1@103.35,57.95 ; D9.1@103.35,48.45 103.4,48.4 v1(103.4,47.6) ; D12.1@103.65,29.85 103.675,29.875 v1(104.6,29.875) ; C118.1@103.94,68 104,67.94 v1(104,67.1) ; v1(104.4,69.6) 105,69 R125.1@105.5,69 ; R136.1@104.97,59.5 v1(105.9,59.5) ; v1(105.7,57.8) 105.795,57.8 105.995,58 C119.1@106.56,58 ; v1(105.8,56.2) R118.1@106.53,56.2 ; C25.1@106.1,31.36 106.14,31.4 v1(107,31.4) ; v1(106.5,46.6) 106.5,48.07 R119.1@106.63,48.2 ; D34.1@106.55,62.25 106.6,62.2 v1(107.425,62.2) ; v1(107.425,64.869) 107.425,64.015 C23.1@107.44,64 ; C22.1@107.44,52.5 C111.1@107.44,51 v1(108.125,51) ; C110.1@107.44,54 v1(108.125,54) ; v1(107.6,44.725) 107.6,44.785 108.015,45.2 R38.1@108.53,45.2 ; R39.1@109.87,57.9 109.87,58.454 110.175,58.759 v1(110.175,58.821) ; v1(116.8,42.1) 116.8,42.87 R35.1@116.83,42.9 ; v1(116.8,56) 116.8,56.77 R34.1@116.83,56.8 ; R36.1@116.83,27.3 116.8,27.33 v1(116.8,28.1) 116.8,28.97 R37.1@116.83,29
  Top Layer w0.5: v1(77.8,56.1) 78.429,55.471 79.079,55.471 R71.2@79.1,55.45 v1(79.1,56.2) ; R71.2@79.121,55.471 79.771,55.471 v1(80.4,56.1)
AN_A0__VBEMF_U/IU(1): C110.2 D8.3 U5.5 X15.B6 X19.9 | length 59.3
  Top Layer w0.15: U5.5@104.4,52.65 104.522,52.772 105.317,52.772 106.532,53.987 106.588,53.987 106.89,53.685 106.89,53.597 107.212,53.275 108.925,53.275 109.3,52.9 113.298,52.9 X19.9@114.636,51.562 ; D8.3@105.7,57.2 105.525,57.2 105.3,56.975 105.3,54.7 106,54 C110.2@106.56,54 ; v1(115.8,21.1) 118.224,21.1 118.649,21.525 120.375,21.525 121.9,20 122.399,20 123.659,18.74 126.09,18.74 X15.B6@126.095,18.735
  Int2 (Sign) w0.15: X19.9@114.61,51.562 114.61,51.29 116.325,49.575 116.325,41.903 116.5,41.728 116.5,32.672 115.8,31.972 v1(115.8,21.1)
AN_A1_VBEMF_V/IV(1): C109.2 D7.3 U5.10 X15.B7 X19.11 | length 70.6
  Top Layer w0.15: U5.10@98.6,52.65 98.65,52.6 99.5,52.6 99.9,53 v1(99.9,53.8) 99.9,55.94 100.21,56.25 100.21,56.265 C109.2@100.352,56.407 ; D7.3@98.75,56.4 100.36,56.4 C109.2@100.46,56.5 ; X19.11@114.636,49.022 117.678,49.022 v1(117.7,49)
  Int2 (Sign) w0.15: v1(116.6,19.6) 116.6,23.6 118.3,25.3 118.3,39.5 117.325,40.475 117.325,41.301 118.425,42.401 118.425,45.399 117.5,46.324 117.5,48.1 117.7,48.3 v1(117.7,49)
  Bottom Layer w0.15: v1(99.9,53.8) 104.653,53.8 108.016,50.437 112.21,50.437 ; 112.264,50.436 cw(c112.358,50.553) 112.263,50.437 112.21,50.437 ; X19.11@114.346,49.148 114.484,49.148 X19.11@114.61,49.022 ; X19.11@114.636,49.022 114.407,49.251 113.649,49.251 112.463,50.437 112.264,50.437 112.21,50.437 ; v1(116.6,19.6) 116.695,19.6 116.805,19.71 122.689,19.71 123.369,19.03 125.011,19.03 125.986,20.005 X15.B7@128,20.005
AN_A2_VBEMF_W/IW(1): C108.2 D6.3 U5.12 X15.B8 X19.13 | length 66.8
  Top Layer w0.15: C108.2@98.14,47.5 D6.3@101.425,47.5 ; U5.12@98.6,51.35 98.75,51.2 99.393,51.2 101.2,49.393 101.2,47.725 D6.3@101.425,47.5 ; v1(102.6,47.55) 101.7,47.55 D6.3@101.65,47.5 D6.3@101.425,47.5 ; X19.13@114.61,46.482 118.482,46.482 v1(119.2,47.2)
  Int2 (Sign) w0.15: v1(119.2,47.2) 119.2,44.442 119.025,44.267 119.025,41.603 119.075,41.553 119.075,23.625 120.7,22 v1(120.7,20.3)
  Int3 (Sign) w0.15: v1(102.6,42.8) v1(102.6,47.55) ; v1(109.7,43.075) 109.7,43.5 111.4,45.2 113.328,45.2 X19.13@114.61,46.482
  Bottom Layer w0.15: v1(102.6,42.8) 102.695,42.8 102.97,43.075 v1(109.7,43.075) ; v1(120.7,20.3) 122.822,20.3 123.797,21.275 X15.B8@126.095,21.275
AN_A3_IAVG/IDCLink(1): C111.2 D9.3 R30.1 R35.2 U5.3 X15.B9 | length 56.4
  Top Layer w0.15: U5.3@104.4,51.35 106.195,51.35 C111.2@106.545,51 ; 105.65,47.8 105.65,50.105 C111.2@106.545,51 ; v1(117.3,50.2) 114.381,50.2 113.806,50.775 112.975,50.775 112.637,50.437 107.05,50.437 106.89,50.597 106.89,50.685 106.575,51 C111.2@106.56,51 C111.2@106.545,51 ; v1(117.8,40.8) 117.8,42.9 117.8,43.97 R30.1@117.77,44 117.8,44.03 v1(117.8,44.7) ; v1(117.9,23) 117.995,23 118.155,22.84 122.84,22.84 123.52,23.52 124.78,23.52 125.755,22.545 X15.B9@128,22.545
  Int2 (Sign) w0.15: v1(117.3,50.2) 117.275,50.175 117.275,49.725 117.1,49.55 117.1,45.4 v1(117.8,44.7) ; v1(117.8,40.8) 118.7,39.9 118.7,25.2 117.9,24.4 v1(117.9,23)
AN_A4_VDCLink: C26.2 D12.3 U21.3 X15.B16 X19.8 | length 61.2
  Top Layer w0.15: C26.2@99.7,32.94 99.7,32.955 100.295,33.55 U21.3@101.2,33.55 101.35,33.4 D12.3@101.35,30.8 108.096,30.8 108.896,30 115.3,30 116.3,31 v1(116.3,31.8) ; X19.8@112.096,54.102 113.221,55.227 116.773,55.227 v1(116.8,55.2)
  Int2 (Sign) w0.15: v1(116.3,31.8) 116.395,31.8 116.628,32.033 116.633,32.033 116.8,32.2 116.8,41.2 117.275,41.675 117.275,43.625 116.7,44.2 116.7,54.937 116.733,54.97 116.733,55.133 v1(116.8,55.2)
  Bottom Layer w0.15: v1(116.3,31.8) 116.325,31.825 120.475,31.825 121.84,30.46 123.106,30.46 124.081,31.435 X15.B16@126.095,31.435
AN_A5_VBEMF_U/Iu(3): C114.2 D20.3 R28.1 R34.2 U11.5 X15.B28 X15.B45 | length 81.3
  Top Layer w0.15: U11.5@87.1,64.25 88.407,64.25 89.657,65.5 D20.3@92.15,65.5 ; C114.2@91.44,67.7 92.2,66.94 92.2,65.55 D20.3@92.15,65.5 ; v1(93.8,65.3) 92.35,65.3 D20.3@92.15,65.5 ; R34.2@117.77,56.8 R28.1@117.77,57.8 120.326,57.8 120.626,58.1 122.5,58.1 123.8,59.4 124.5,59.4 125.7,58.2 v1(126.6,58.2)
  Int3 (Sign) w0.15: v1(121.078,65.85) 122.936,65.85 123.786,66.7 124.004,66.7 125.569,68.265 X15.B45@128,68.265 128,67.111 126.9,66.011 126.9,65.033 127.2,64.733 127.2,63.974 126.8,63.574 126.8,62.694 127.2,62.294 127.2,61.485 127.025,61.31 127.025,60.163 127.2,59.988 127.2,58.8 v1(126.6,58.2) 127.108,57.692 127.125,57.675 ccw(c128,58.105) 127.2,57.548 127.2,56.216 126.7,55.716 126.7,55.212 127.2,54.712 127.2,53.891 126.8,53.491 126.8,52.585 127.2,52.185 127.2,51.377 126.8,50.977 126.8,50.098 127.3,49.598 127.3,48.8 126.2,47.7 126.2,46.78 X15.B28@126.095,46.675
  Bottom Layer w0.15: v1(93.8,65.3) 94.1,65 102.458,65 103.308,65.85 v1(121.078,65.85)
AN_A6_VBEMF_V/Iv(3): C113.2 D11.3 U11.10 X15.B29 X15.B46 | length 79.2
  Top Layer w0.15: C113.2@78.74,62.9 78.74,65.115 79.125,65.5 D11.3@79.35,65.5 79.575,65.275 79.575,64.388 79.663,64.3 81.25,64.3 U11.10@81.3,64.25 81.35,64.2 v1(85.4,64.2) ; v1(121.1,65.2) 121.7,65.8 122.7,65.8 123.9,67 124.6,67 126.095,68.495 X15.B46@126.095,69.535
  Int2 (Sign) w0.15: X15.B46@126.095,69.535 128.765,69.535 129.5,68.8 129.5,49.445 X15.B29@128,47.945
  Bottom Layer w0.15: v1(85.4,64.2) 90.736,64.2 90.911,64.025 93.729,64.025 94.379,64.675 104.446,64.675 104.727,64.394 114.793,64.394 115,64.6 120.5,64.6 v1(121.1,65.2)
AN_A7_VBEMF_W/Iw(3): C112.2 D10.3 U11.12 X15.B30 X15.B44 | length 77.3
  Top Layer w0.15: C112.2@78.64,57 78.64,59.015 79.125,59.5 D10.3@79.35,59.5 79.5,59.65 79.5,61.793 80.507,62.8 81.15,62.8 U11.12@81.3,62.95 81.413,63.063 v1(85.305,63.063) ; v1(121.075,64.2) 121.875,63.4 122.7,63.4 123.8,64.5 124.5,64.5 125.225,65.225 125.225,66.125 X15.B44@126.095,66.995 127.025,66.065 127.025,64.911 127.07,64.866 127.07,63.846 127.025,63.801 127.025,62.47 127.07,62.425 127.07,61.356 127.025,61.311 127.025,60.241 127.891,59.375 128.325,59.375 129.5,58.2 129.5,50.606 128.109,49.215 X15.B30@126.095,49.215
  Bottom Layer w0.15: v1(85.305,63.063) 90.792,63.063 91.346,63.618 100.518,63.618 100.8,63.9 115,63.9 115.3,64.2 v1(121.075,64.2)
AN_B0_VBEMF_U/IU(2): C118.2 D33.3 U9.5 X15.B17 X19.10 | length 69
  Top Layer w0.15: D33.3@98.85,68 C118.2@103.06,68 103.1,67.96 v1(103.1,67) 103.06,66.96 103.06,64.947 103.607,64.4 104.25,64.4 U9.5@104.4,64.25
  Int2 (Sign) w0.15: X19.10@112.096,51.562 112.4,51.258 112.4,50.861 112.4,50.799 cw(c109.4,47.8) 112.7,50.466 112.7,50.26 cw(c90.485,35.649) 113.38,49.17 cw(c113.25,49.095) 113.4,49.095 v1(113.4,35.5)
  Int3 (Sign) w0.15: v1(110.3,51.5) 110.3,53.9 108.825,55.375 108.825,63.721 110.9,65.796 v1(110.9,67.8)
  Bottom Layer w0.15: v1(103.1,67) 103.9,67.8 v1(110.9,67.8) v1@111.002,67.8 ; v1(110.3,51.5) 110.331,51.531 112.039,51.531 X19.10@112.07,51.562 ; v1(113.4,35.5) 113.95,34.95 122.689,34.95 123.369,34.27 124.004,34.27 125.569,32.705 X15.B17@128,32.705
AN_B1_VBEMF_V/IV(2): C117.2 D32.3 U9.10 X15.B18 X19.12 | length 68.1
  Top Layer w0.15: v1(96.7,60.6) 96.7,59.55 D32.3@96.65,59.5 96.425,59.5 96.2,59.725 96.2,60.515 95.94,60.775 C117.2@95.94,61.8 v1(97,61.8) ; v1(97,64.2) 98.55,64.2 U9.10@98.6,64.25 ; v1(108.3,35.8) 110.5,35.8 111.25,35.05 115.25,35.05 115.9,35.7 120.193,35.7 120.693,35.2 122.7,35.2 123.925,33.975 X15.B18@126.095,33.975
  Int2 (Sign) w0.15: v1(108.3,35.8) 108.347,35.847 108.347,36.275 109.1,37.028 109.1,40.528 110.2,41.628 110.2,47.152 112.07,49.022 111.261,49.831 111.261,50.439 110.945,50.755 110.945,58.925 v1(110.47,59.4)
  Int3 (Sign) w0.15: v1(97,61.8) v1(97,64.2)
  Bottom Layer w0.15: v1(96.7,60.6) 109.27,60.6 v1(110.47,59.4)
AN_B2_VBEMF_W/IW(2): C116.2 D31.3 U9.12 X15.B19 X19.14 | length 69.1
  Top Layer w0.15: C116.2@95.94,63.1 C116.2@95.94,63.3 ; D31.3@96.65,65.5 96.65,64.65 95.94,63.94 C116.2@95.94,63.3 ; v1(101.5,62.9) 98.65,62.9 U9.12@98.6,62.95 97.115,62.95 97,63.065 96.175,63.065 C116.2@95.94,63.3
  Int2 (Sign) w0.15: v1(109.6,34.6) 109.6,40.604 110.5,41.504 110.5,44.886 X19.14@112.096,46.482
  Int3 (Sign) w0.15: v1(109.6,34.6) 110.05,35.05 115.175,35.05 v1(116.025,34.2) ; v1(110.6,62.8) 109.8,62 109.8,59.082 109.7,58.982 109.7,55 110.775,53.925 110.775,51.303 110.062,50.591 110.062,49.439 111.1,48.401 111.1,47.452 X19.14@112.07,46.482 ; v1(122.939,33.029) 124.11,34.2 124.9,34.2 125.9,35.2 127.955,35.2 X15.B19@128,35.245
  Bottom Layer w0.15: v1(101.5,62.9) 101.55,62.85 110.55,62.85 v1(110.6,62.8) ; v1(116.025,34.2) 118.848,34.2 120.048,33 122.91,33 v1(122.939,33.029)
AN_B3__IAVG_IDCLink(2): C119.2 D34.3 R31.2 R38.2 U9.3 X15.B20 | length 60.5
  Top Layer w0.15: U9.3@104.4,62.95 108.15,62.95 108.85,62.25 D34.3@108.85,61.3 108.1,61.3 107.425,60.625 107.425,59.437 107.44,59.422 C119.2@107.44,58 107.447,57.993 107.447,57.553 107.985,57.015 107.985,56.206 108.591,55.599 108.591,54.709 v1(109.5,53.8) ; R31.2@109.47,44.1 R38.2@109.47,45.2 ; v1@109.761,46.064 109.47,45.773 R38.2@109.47,45.2 ; v1(130.8,44.8) 129.336,44.8 128.836,44.3 127.5,44.3 126.69,45.11 125.41,45.11 124.6,44.3 123.6,44.3 122.7,45.2 R38.2@109.47,45.2
  Int3 (Sign) w0.15: v1(109.5,53.8) 109.5,46.363 109.725,46.138 v1(109.725,46.1) ; X15.B20@126.095,36.515 130.685,36.515 v1(130.7,36.5)
  Bottom Layer w0.15: v1(130.7,36.5) 130.75,36.55 130.75,44.75 v1(130.8,44.8)
AN_B4_Vac0: C135.1 R9.2 U1.67 X15.A42 X17.11 X18.1 | length 164.1
  Top Layer w0.15: X18.1@7.54,51.64 7.6,51.58 v1(7.6,47.4) ; R9.2@44.6,32.86 C135.1@44.6,33.96 44.64,34 v1(45.5,34) ; U1.67@90.1,50.2 90.1,49.225 90.4,48.925 v1(90.4,48.9)
  Int2 (Sign) w0.15: v1(90.4,48.9) 90.4,48.936 90.1,49.236 v1(90.1,60.9) 90.1,66.8 90.6,67.3 90.6,68.2 89.909,68.891 89.909,70.015 X17.11@91.776,71.882
  Int3 (Sign) w0.15: v1(7.6,47.4) 43.928,47.4 44.328,47 v1(45,47) 69.2,47 70.4,48.2 78.9,48.2 80.2,49.5 v1(80.2,50)
  Bottom Layer w0.15: v1(45,47) 45,36.6 45.5,36.1 v1(45.5,34) ; v1(80.2,50) 82.1,50 82.4,49.7 89.6,49.7 v1(90.4,48.9) ; v1(90.1,60.9) 91.725,62.525 100.125,62.525 100.975,63.375 111.125,63.375 111.31,63.19 121.02,63.19 X15.A42@122.285,64.455
AN_B5_Vac1: C136.1 R10.2 U1.68 X15.A43 X17.9 | length 106
  Top Layer w0.15: v1(69.1,27.5) 70.5,27.5 70.96,27.96 R10.2@70.96,29 70.94,29.02 C136.1@70.94,30.1 ; v1(89.6,48.9) U1.68@89.6,50.2
  Int2 (Sign) w0.15: v1(69.1,27.5) v1(69.1,45.9) ; X17.9@89.236,71.882 89.2,71.846 89.2,70.1 89.4,69.9 v1(89.4,68.1) 89.4,57.2 88.9,56.7 88.9,55.9 89.575,55.225 89.575,48.925 v1(89.6,48.9)
  Int3 (Sign) w0.15: v1(69.1,45.9) 70.1,46.9 78.3,46.9 80.8,49.4 v1(81.4,49.4)
  Bottom Layer w0.15: v1(81.4,49.4) 89.1,49.4 v1(89.6,48.9) ; v1(89.4,68.1) 89.7,68.4 93.776,68.4 94.151,68.775 119.025,68.775 122.075,65.725 X15.A43@124.19,65.725
AN_B6__BrakeTemp1: R29.2 R39.2 U1.69 X15.B15 X15.B48 | length 114.5
  Top Layer w0.15: U1.69@89.1,50.2 v1(89.1,51.5) ; R29.2@108.93,56.6 R39.2@108.93,57.9 108.93,58.93 v1(109.3,59.3) 110,60 110,63.9 116.8,70.7 122.289,70.7 123.664,72.075 X15.B48@126.095,72.075
  Int2 (Sign) w0.15: v1(89.1,51.5) 89.1,47.5 91.6,45 v1(91.6,39.9) ; v1(108.6,37.6) 106.9,39.3 106.9,46.328 107.025,46.453 107.025,46.897 109,48.872 109,59 v1(109.3,59.3) ; X15.B15@128,30.165 129.325,31.49 129.325,38.975 v1(129.3,39)
  Int3 (Sign) w0.15: v1(108.6,37.6) 115.216,37.6 v1(115.725,38.109)
  Bottom Layer w0.15: v1(91.6,39.9) 92.7,38.8 93.858,38.8 94.333,38.325 101.682,38.325 101.957,38.6 107.6,38.6 v1(108.6,37.6) ; v1(115.725,38.109) 118.797,38.109 119.416,37.49 122.689,37.49 123.369,36.81 125.011,36.81 126.281,38.08 126.499,38.08 127.419,39 v1(129.3,39)
AN_B7_IAVG_IDCLink(3): C115.2 D29.3 U11.3 X15.A46 X15.B31 X19.7 | length 76.4
  Top Layer w0.15: U11.3@87.1,62.95 85.85,62.95 85.7,62.8 85.7,60.1 86.3,59.5 D29.3@91.05,59.5 ; v1(90.6,54.9) 91.2,55.5 91.2,56.6 91,56.8 91,59.45 D29.3@91.05,59.5 ; C115.2@92.44,60.5 92.425,60.5 92.19,60.265 92.19,59.99 91.712,59.512 91.062,59.512 D29.3@91.05,59.5 ; X19.7@114.636,54.102 115.998,54.102 119.32,50.78 122.78,50.78 v1(123.9,51.9) ; v1(117.5,60.5) 120.175,63.175 120.175,67.425 X15.A46@122.285,69.535 ; X19.7@114.61,54.102 X19.7@114.611,54.101
  Int2 (Sign) w0.15: X19.7@114.636,54.102 114.636,54.472 117.5,57.336 v1(117.5,60.5)
  Int3 (Sign) w0.15: v1(110.3,55.3) 113.438,55.3 X19.7@114.636,54.102
  Bottom Layer w0.15: v1(90.6,54.9) 91.8,56.1 105.264,56.1 105.764,55.6 110,55.6 v1(110.3,55.3) ; v1(123.9,51.9) 124.571,51.9 125.986,50.485 X15.B31@128,50.485
AUX_LED#: D4.1 U7.1 | length 8.5
  Top Layer w0.15: v1(9.5,25.5) D4.1@10.65,25.5 ; U7.1@15,22.75 v1(15,23.8)
  Int2 (Sign) w0.15: v1(9.5,25.5) 13.4,25.5 14.864,24.036 14.864,24.031 15,23.895 v1(15,23.8)
CAN1_RX: U1.42 U4.6 X17.21 | length 120.7
  Top Layer w0.15: U1.42@95.05,39.25 99.45,39.25 99.7,39 v1(100.2,39)
  Top Layer w0.2: U4.6@37.57,6.865 37.635,6.8 v1(40.5,6.8) ; v1(86.075,39) 86.156,39 86.256,38.9 87.44,38.9 87.565,39.025 89.725,39.025 90.1,39.4 92.151,39.4 92.301,39.25 U1.42@95.05,39.25
  Int2 (Sign) w0.2: v1(40.5,6.8) 41.1,6.8 41.9,7.6 41.9,8.647 49.3,16.047 49.3,19.3 51,21 v1(51,31.8)
  Int3 (Sign) w0.15: v1(100.2,39) 100.2,42.8 101.1,43.7 101.1,55 100.7,55.4 100.7,63 105,67.3 105,69.8 104.476,70.324 X17.21@104.476,71.882
  Bottom Layer w0.2: v1(51,31.8) 57.144,31.8 62.544,37.2 69.9,37.2 70.7,38 83.4,38 84,38.6 85.675,38.6 v1(86.075,39)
